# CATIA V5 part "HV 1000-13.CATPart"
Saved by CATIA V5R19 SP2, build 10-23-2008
Part number: HV 1000-13
Bounding box of the stored display mesh (mm): x -24.865 to 24.865, y -24.997 to 24.997, z 0 to 83
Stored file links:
  C:\Users\Bora\Desktop\3D KATI MODEL- CATIA PART\HV serisi\HV 1000\HV 1000-13.CATPart
  C:\Program Files\Dassault Systemes\B19\intel_a\reffiles\standard\MetricThickPitch.txt
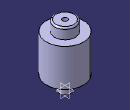
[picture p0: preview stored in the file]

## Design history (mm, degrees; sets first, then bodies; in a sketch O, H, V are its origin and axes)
Body1 (main body)
  Sketch1 on yz-plane, origin (0, 0, 0), H (0, 1, 0), V (0, 0, 1)
    point P1 (14, 81)
    point P3 (14, 81)
    point P8 (8, 17)
    point P10 (8, 1)
    point P11 (8, 17)
    point P12 (8, 1)
    arc A1 centre (12, 81) radius 2 from (14, 81) to (12, 83) ccw
    line L1 (14, 81) -> (14, 69)
    arc A2 centre (8, 18) radius 1 from (8, 19) to (8, 17) ccw
    line L2 (7, 0) -> (8, 1)
    line L3 (8, 17) -> (8, 1)
    line L4 (12, 83) -> (0, 83)
    point P13 (0, 83)
    line L5 (14, 69) -> (25, 69)
    line L6 (8, 19) -> (25, 19)
    line L7 (7, 0) -> (0, 0)
    line L8 (25, 69) -> (25, 19)
    tangency: L4 A1, L6 A2
    coincidence: P13 V, P1 P3, P8 P11, P10 P12
    horizontal: L5 H, L7 H
    vertical: L8 V
  Shaft1: profile Sketch1, axis Sketch1.V, angle 360
  Sketch2 on face of Shaft1 from Sketch1.L7, origin (0, 0, 0), H (1, 0, 0), V (0, -1, 0)
    point P1 (0, 0)
  Hole1: placed by Sketch2, at (0, 0, 0) direction (0, 0, 1), diameter 13.835, depth 19, threaded "M16", thread diameter 16, thread depth 19, pitch 2
  Sketch3 on face of Shaft1 from Sketch1.L4, origin (0, 0, 83), H (1, 0, 0), V (0, 1, 0)
    point P1 (0, 0)
  Hole2: placed by Sketch3, at (0, 0, 83) direction (0, 0, -1), diameter 6.647, depth 15, threaded "M8", thread diameter 8, thread depth 15, pitch 1.25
